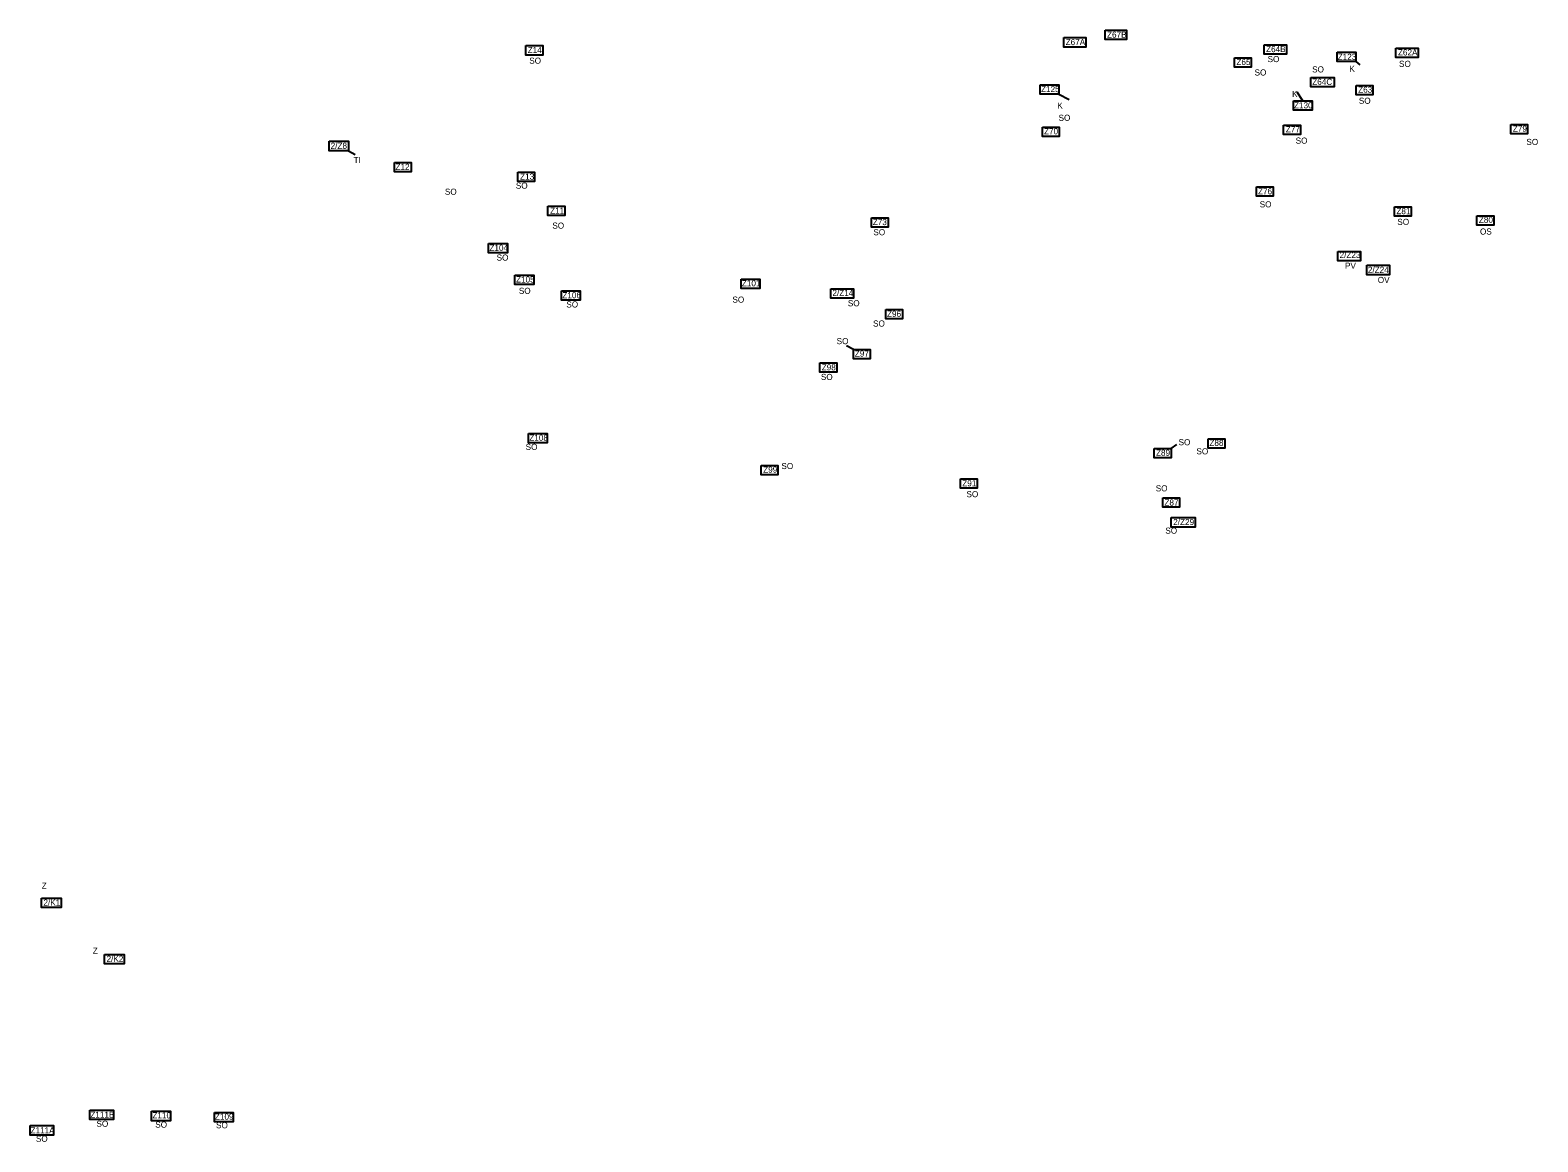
# Model space of a CAD drawing. Extents: x -443485 to -436070, y -1146628 to -1129894.
# Drawn here: x -443485 to -441018, y -1133480 to -1131660 of the extents above; entities that cross this region are included whole.
import ezdxf

# ---------------------------------------------------------------- set-up
doc = ezdxf.new("R2010")
doc.units = 0
for name, color, linetype in [('Vrstva 3', 7, 'Continuous'), ('Vrstva 4', 7, 'Continuous'), ('Vrstva 8', 7, 'Continuous')]:
    doc.layers.add(name, color=color, linetype=linetype)

msp = doc.modelspace()

# ---------------------------------------------------------------- linework, layer by layer
at = {"layer": 'Vrstva 3'}
for p, q in [((-442963.8, -1131857.8), (-442953.2, -1131864)), ((-442137.9, -1132182.9), (-442149.2, -1132176.8)), ((-441618.1, -1132344.9), (-441608.8, -1132338.2))]:
    msp.add_line(p, q, dxfattribs=at)
for points in [[(-441793.5, -1131672.7), (-441757.6, -1131672.7), (-441757.6, -1131688.1), (-441793.5, -1131688.1)], [(-441725.8, -1131660.5), (-441690.7, -1131660.5), (-441690.7, -1131675.9), (-441725.8, -1131675.9)], [(-442673.5, -1131685.8), (-442646.2, -1131685.8), (-442646.2, -1131701.2), (-442673.5, -1131701.2)], [(-441465.9, -1131684.6), (-441429.2, -1131684.6), (-441429.2, -1131700), (-441465.9, -1131700)], [(-441250.1, -1131690.1), (-441213.9, -1131690.1), (-441213.9, -1131705.5), (-441250.1, -1131705.5)], [(-441514.3, -1131705.6), (-441487, -1131705.6), (-441487, -1131721), (-441514.3, -1131721)], [(-441389.1, -1131737.8), (-441351.3, -1131737.8), (-441351.3, -1131753.2), (-441389.1, -1131753.2)], [(-441315.3, -1131751.1), (-441287.9, -1131751.1), (-441287.9, -1131766.5), (-441315.3, -1131766.5)], [(-441828.6, -1131819.1), (-441801.2, -1131819.1), (-441801.2, -1131834.4), (-441828.6, -1131834.4)], [(-441433.8, -1131815.7), (-441406.5, -1131815.7), (-441406.5, -1131831.1), (-441433.8, -1131831.1)], [(-441062.2, -1131815.1), (-441034.8, -1131815.1), (-441034.8, -1131830.4), (-441062.2, -1131830.4)], [(-442995.6, -1131842.4), (-442963.8, -1131842.4), (-442963.8, -1131857.8), (-442995.6, -1131857.8)], [(-442888.8, -1131877), (-442861.4, -1131877), (-442861.4, -1131892.4), (-442888.8, -1131892.4)], [(-442686.7, -1131892.8), (-442659.4, -1131892.8), (-442659.4, -1131908.2), (-442686.7, -1131908.2)], [(-441478.3, -1131917), (-441450.9, -1131917), (-441450.9, -1131932.4), (-441478.3, -1131932.4)], [(-442637.5, -1131948.5), (-442610.2, -1131948.5), (-442610.2, -1131963.9), (-442637.5, -1131963.9)], [(-442108.4, -1131967.4), (-442081, -1131967.4), (-442081, -1131982.8), (-442108.4, -1131982.8)], [(-441252.4, -1131949.4), (-441225, -1131949.4), (-441225, -1131964.8), (-441252.4, -1131964.8)], [(-441117.5, -1131964.1), (-441090.1, -1131964.1), (-441090.1, -1131979.5), (-441117.5, -1131979.5)], [(-442734.8, -1132009.7), (-442704, -1132009.7), (-442704, -1132025.1), (-442734.8, -1132025.1)], [(-441345.2, -1132022.4), (-441307.9, -1132022.4), (-441307.9, -1132037.8), (-441345.2, -1132037.8)], [(-441345.2, -1132022.4), (-441307.9, -1132022.4), (-441307.9, -1132037.8), (-441345.2, -1132037.8)], [(-442691.5, -1132061.4), (-442660.7, -1132061.4), (-442660.7, -1132076.8), (-442691.5, -1132076.8)], [(-442321.4, -1132067.9), (-442290.7, -1132067.9), (-442290.7, -1132083.3), (-442321.4, -1132083.3)], [(-441297.9, -1132045.3), (-441260.7, -1132045.3), (-441260.7, -1132060.7), (-441297.9, -1132060.7)], [(-442615.4, -1132087.1), (-442584.7, -1132087.1), (-442584.7, -1132102.5), (-442615.4, -1132102.5)], [(-442174.9, -1132083.6), (-442137.5, -1132083.6), (-442137.5, -1132098.9), (-442174.9, -1132098.9)], [(-442085, -1132117.4), (-442057.6, -1132117.4), (-442057.6, -1132132.8), (-442085, -1132132.8)], [(-442137.9, -1132182.9), (-442110.5, -1132182.9), (-442110.5, -1132198.2), (-442137.9, -1132198.2)], [(-442192.5, -1132204.9), (-442165.1, -1132204.9), (-442165.1, -1132220.3), (-442192.5, -1132220.3)], [(-442669.5, -1132320.3), (-442638.8, -1132320.3), (-442638.8, -1132335.7), (-442669.5, -1132335.7)], [(-441557.5, -1132329), (-441530.2, -1132329), (-441530.2, -1132344.4), (-441557.5, -1132344.4)], [(-441645.5, -1132344.9), (-441618.1, -1132344.9), (-441618.1, -1132360.3), (-441645.5, -1132360.3)], [(-442288.6, -1132372.9), (-442261.2, -1132372.9), (-442261.2, -1132388.3), (-442288.6, -1132388.3)], [(-441962.6, -1132394.5), (-441935.3, -1132394.5), (-441935.3, -1132409.9), (-441962.6, -1132409.9)], [(-441631.5, -1132425.8), (-441604.1, -1132425.8), (-441604.1, -1132441.2), (-441631.5, -1132441.2)], [(-441617.7, -1132458.1), (-441578.7, -1132458.1), (-441578.7, -1132473.5), (-441617.7, -1132473.5)], [(-443466.2, -1133080.6), (-443434.2, -1133080.6), (-443434.2, -1133096), (-443466.2, -1133096)], [(-443363, -1133172.7), (-443330.8, -1133172.7), (-443330.8, -1133188.1), (-443363, -1133188.1)], [(-443387, -1133427.6), (-443348.5, -1133427.6), (-443348.5, -1133443), (-443387, -1133443)], [(-443286.1, -1133429.5), (-443255.3, -1133429.5), (-443255.3, -1133444.9), (-443286.1, -1133444.9)], [(-443183.4, -1133431.3), (-443152.6, -1133431.3), (-443152.6, -1133446.7), (-443183.4, -1133446.7)], [(-443484.8, -1133452.9), (-443446.4, -1133452.9), (-443446.4, -1133468.3), (-443484.8, -1133468.3)]]:
    msp.add_lwpolyline(points, close=True, dxfattribs=at)
at = {"layer": 'Vrstva 8'}
for p, q in [((-441315.6, -1131712), (-441308.9, -1131717.3)), ((-441801.4, -1131765.3), (-441784.8, -1131773.8)), ((-441402.4, -1131775.9), (-441411.7, -1131761.9))]:
    msp.add_line(p, q, dxfattribs=at)
for points in [[(-441346.4, -1131696.6), (-441315.6, -1131696.6), (-441315.6, -1131712), (-441346.4, -1131712)], [(-441832.2, -1131749.9), (-441801.4, -1131749.9), (-441801.4, -1131765.3), (-441832.2, -1131765.3)], [(-441417.8, -1131775.9), (-441387.1, -1131775.9), (-441387.1, -1131791.3), (-441417.8, -1131791.3)]]:
    msp.add_lwpolyline(points, close=True, dxfattribs=at)

# ---------------------------------------------------------------- texts
at = {"layer": 'Vrstva 3'}
for s, p in [('Z67B', (-441722.8, -1131672.8)), ('Z14', (-442670.7, -1131698)), ('Z67A', (-441790.5, -1131685)), ('Z64B', (-441462.6, -1131696.5)), ('Z62A', (-441246.8, -1131701.9)), ('Z65', (-441511.1, -1131717.6)), ('Z64C', (-441387, -1131750)), ('Z64', (-441387, -1131750)), ('Z63', (-441311.9, -1131762.9)), ('Z70', (-441825.9, -1131831)), ('Z77', (-441430.3, -1131827.7)), ('Z79', (-441058.8, -1131826.7)), ('2/Z8', (-442993.1, -1131854.7)), ('Z12', (-442887.1, -1131889.2)), ('Z13', (-442683.2, -1131905.1)), ('Z76', (-441475.8, -1131929.2)), ('Z11', (-442634, -1131960.8)), ('Z73', (-442106.1, -1131979.5)), ('Z81', (-441249.4, -1131961.6)), ('Z80', (-441114.4, -1131975.9)), ('Z104', (-442733.3, -1132021.6)), ('2/Z23', (-441342.3, -1132033.4)), ('Z105', (-442689.8, -1132073.4)), ('2/Z24', (-441296, -1132057.6)), ('Z106', (-442614, -1132099.2)), ('Z101', (-442320.3, -1132079.6)), ('2/Z14', (-442172.1, -1132095.4)), ('Z96', (-442082.8, -1132129.6)), ('Z97', (-442135.5, -1132194.7)), ('Z98', (-442189.6, -1132217.2)), ('Z108', (-442668.1, -1132332.4)), ('Z88', (-441555.3, -1132340.8)), ('Z89', (-441642.7, -1132357)), ('Z99', (-442285.4, -1132384.6)), ('Z91', (-441959.7, -1132406.9)), ('Z87', (-441628.9, -1132438.4)), ('2/Z29', (-441614.5, -1132470.3)), ('2/K1', (-443463.1, -1133092.9)), ('2/K2', (-443359.8, -1133185)), ('Z111B', (-443386.3, -1133440.1)), ('Z110', (-443284.8, -1133441.2)), ('Z109', (-443182.5, -1133443.2)), ('Z111A', (-443484.1, -1133465.5))]:
    msp.add_text(s, height=10, dxfattribs=at).set_placement(p)
at = {"layer": 'Vrstva 4'}
for s, p in [('SO', (-442668.2, -1131715.4)), ('SO', (-441460.1, -1131712.8)), ('SO', (-441387.2, -1131729.7)), ('K', (-441326.3, -1131728.7)), ('SO', (-441245, -1131720.6)), ('SO', (-441481.4, -1131734.7)), ('K', (-441419.9, -1131769.8)), ('SO', (-441310.8, -1131781)), ('K', (-441804.1, -1131788.9)), ('SO', (-441802.1, -1131808.9)), ('SO', (-441414.2, -1131846.2)), ('SO', (-441036.6, -1131848.4)), ('TI', (-442955.5, -1131878)), ('SO', (-442806.2, -1131929.8)), ('SO', (-442690.1, -1131919.9)), ('SO', (-441473, -1131950.5)), ('SO', (-441247.8, -1131979.2)), ('SO', (-442630.4, -1131985.3)), ('SO', (-442105.1, -1131996.1)), ('OS', (-441112.6, -1131995)), ('SO', (-442721.6, -1132037.6)), ('PV', (-441333.4, -1132050.9)), ('OV', (-441279.8, -1132074.2)), ('SO', (-442685.2, -1132092)), ('SO', (-442607.5, -1132114.3)), ('SO', (-442335.7, -1132106.4)), ('SO', (-442146.9, -1132112.3)), ('SO', (-442105.6, -1132145.5)), ('SO', (-442165.2, -1132174.3)), ('SO', (-442191, -1132232.9)), ('SO', (-442674.1, -1132347.4)), ('SO', (-441605.7, -1132339.7)), ('SO', (-441576.5, -1132354.6)), ('SO', (-442255.6, -1132378.7)), ('SO', (-441643.1, -1132415.2)), ('SO', (-441952.8, -1132424.7)), ('SO', (-441627.4, -1132484.4)), ('Z', (-443465.9, -1133065.4)), ('Z', (-443382.3, -1133171.6)), ('SO', (-443376.3, -1133454.9)), ('SO', (-443280.1, -1133456.3)), ('SO', (-443180.7, -1133457.3)), ('SO', (-443475.4, -1133479.4))]:
    msp.add_text(s, height=10, dxfattribs=at).set_placement(p)
at = {"layer": 'Vrstva 8'}
for s, p in [('Z123', (-441345.4, -1131709.1)), ('Z125', (-441830.8, -1131761.9)), ('Z130', (-441416.9, -1131788.4))]:
    msp.add_text(s, height=10, dxfattribs=at).set_placement(p)

doc.saveas('drawing.dxf')
